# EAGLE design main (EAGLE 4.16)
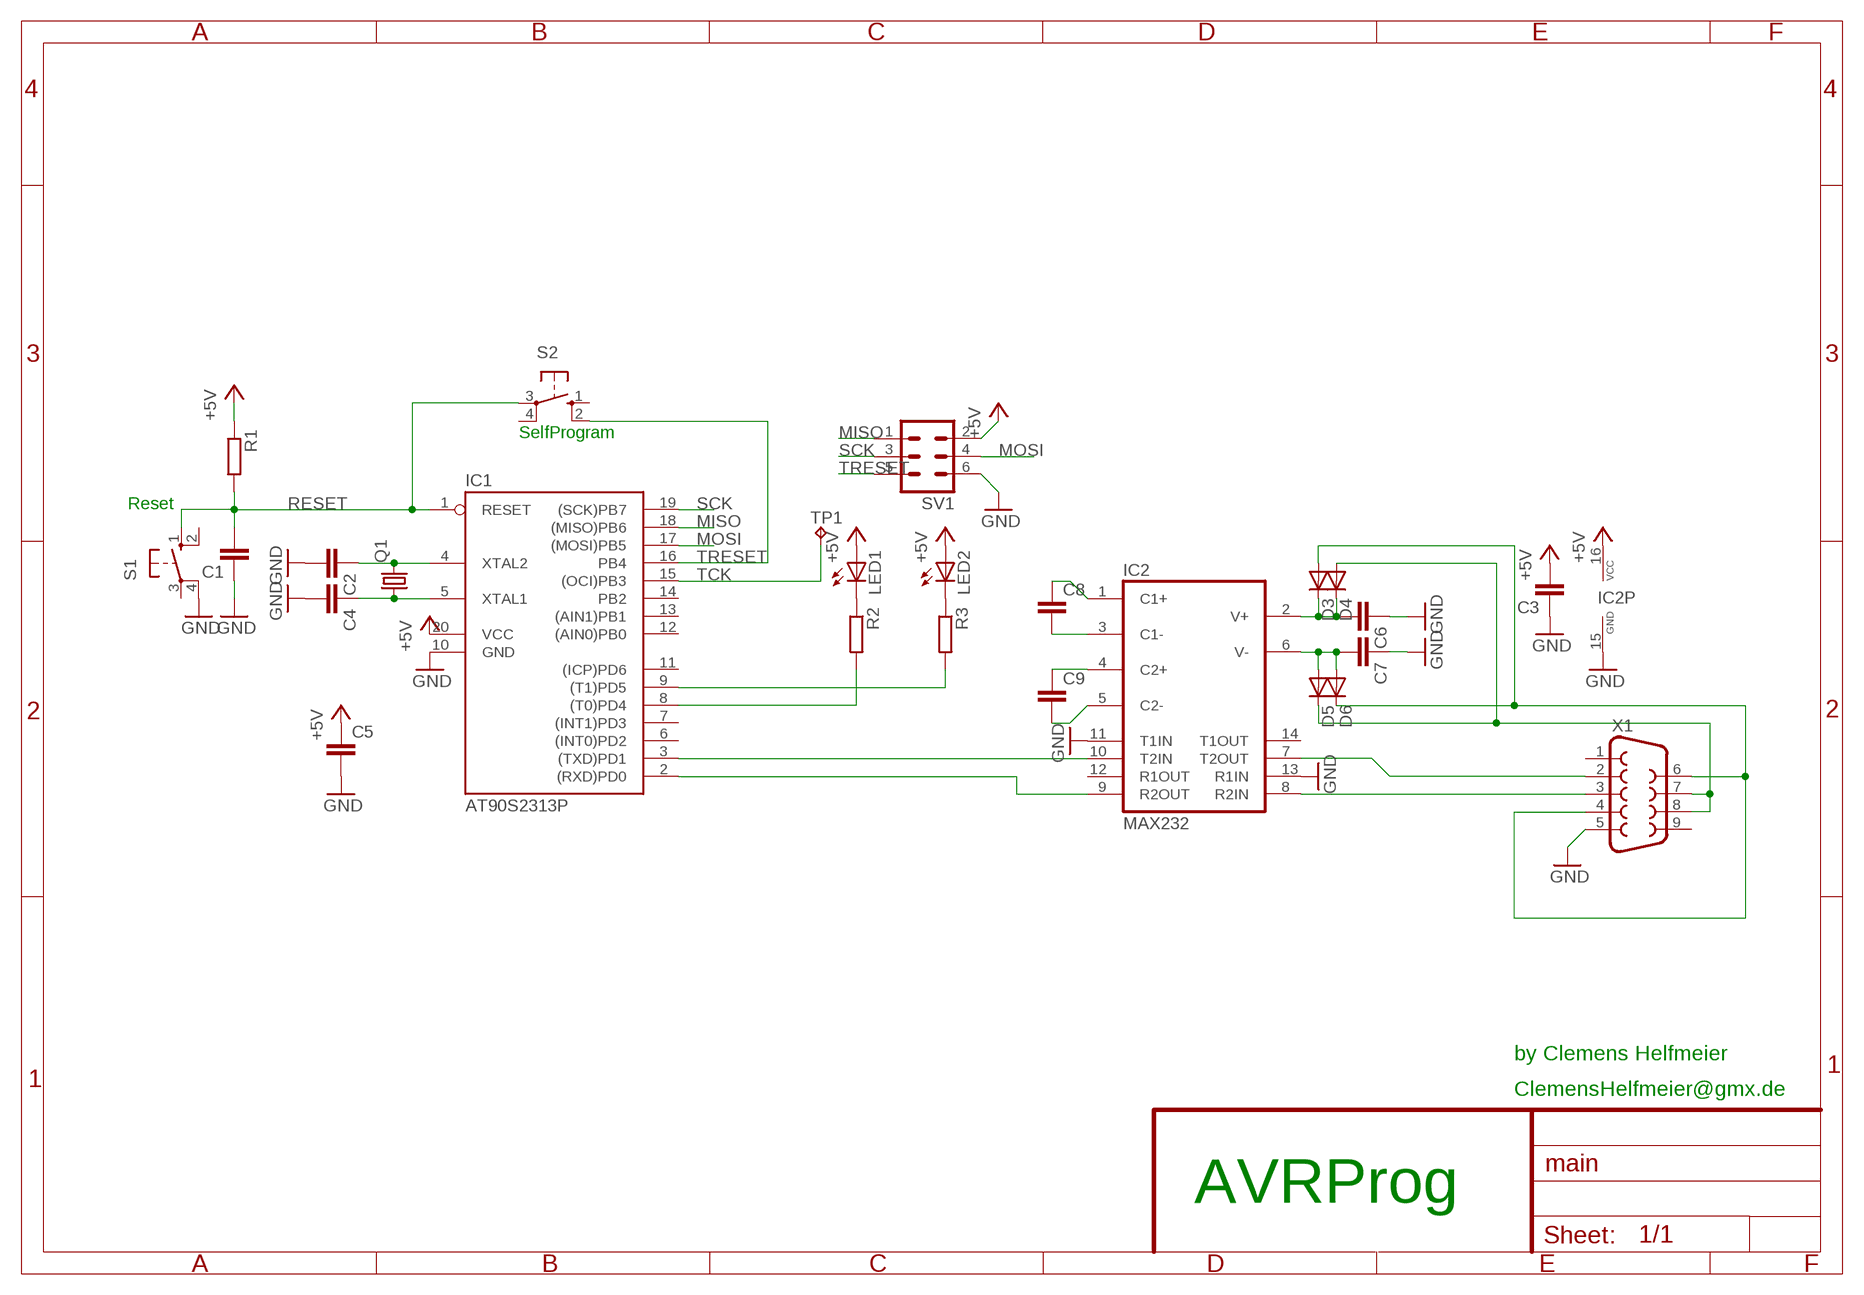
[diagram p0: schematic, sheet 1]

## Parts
C1  C-EU025-024X044  [C025-024X044]
C2  C-EU025-024X044  [C025-024X044]
C3  C-EU025-024X044  [C025-024X044]
C4  C-EU025-024X044  [C025-024X044]
C5  C-EU025-024X044  [C025-024X044]
C6  C-EU025-024X044  [C025-024X044]
C7  C-EU025-024X044  [C025-024X044]
C8  C-EU025-024X044  [C025-024X044]
C9  C-EU025-024X044  [C025-024X044]
D3  DIODE-D-5  [D-5]
D4  DIODE-D-5  [D-5]
D5  DIODE-D-5  [D-5]
D6  DIODE-D-5  [D-5]
IC1  AT90S2313P  [DIL20]
IC2  MAX232  [DIL16]
LED1  LED5MM  [LED5MM]
LED2  LED5MM  [LED5MM]
Q1  CRYTALHC49U-V  [HC49U-V]
R1  R-EU_0204/7  [0204/7]
R2  R-EU_0204/7  [0204/7]
R3  R-EU_0204/7  [0204/7]
S1  10-XX  [B3F-10XX]
S2  10-XX  [B3F-10XX]
SV1  MA03-2W  [MA03-2W]
TP1  TPPAD1-20Y  [P1-20Y]
X1  F09H  [F09H]

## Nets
+5V: C3.2 C5.1 IC1.20(VCC) IC2.16(VCC) LED1.A LED2.A R1.1 SV1.2
GND: C1.1 C2.2 C3.1 C4.2 C5.2 C6.1 C7.1 IC1.10(GND) IC2.11(T1IN) IC2.13(R1IN) IC2.15(GND) S1.4(P1) SV1.6 X1.5
MISO: IC1.18((MISO)PB6) SV1.1
MOSI: IC1.17((MOSI)PB5) SV1.4
N$2: C2.1 IC1.4(XTAL2) Q1.2
N$3: C4.1 IC1.5(XTAL1) Q1.1
N$4: LED1.K(C) R2.1
N$5: LED2.K(C) R3.1
N$6: IC1.8((T0)PD4) R2.2
N$7: IC1.9((T1)PD5) R3.2
N$9: C8.1 IC2.1(C1+)
N$10: C8.2 IC2.3(C1-)
N$11: C9.1 IC2.4(C2+)
N$12: C9.2 IC2.5(C2-)
N$13: C7.2 D5.A D6.A IC2.6(V-)
N$14: C6.2 D3.C D4.C IC2.2(V+)
N$15: IC2.7(T2OUT) X1.2
N$16: IC2.8(R2IN) X1.3
N$17: D3.A D6.C X1.4 X1.6
N$18: D4.A D5.C X1.7 X1.8
N$20: IC1.3((TXD)PD1) IC2.10(T2IN)
N$21: IC1.2((RXD)PD0) IC2.9(R2OUT)
RESET: C1.2 IC1.1(RESET) R1.2 S1.1(S) S2.3(P)
SCK: IC1.19((SCK)PB7) SV1.3
TCK: IC1.15((OCI)PB3) TP1.1(TP)
TRESET: IC1.16(PB4) S2.2(S1) SV1.5
Unconnected: IC1.6((INT0)PD2) IC1.7((INT1)PD3) IC1.11((ICP)PD6) IC1.12((AIN0)PB0) IC1.13((AIN1)PB1) IC1.14(PB2) IC2.12(R1OUT) IC2.14(T1OUT) S1.2(S1) S1.3(P) S2.1(S) S2.4(P1) X1.1 X1.9

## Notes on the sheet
- SelfProgram
- Reset
- by Clemens Helfmeier
- ClemensHelfmeier@gmx.de
- AVRProg

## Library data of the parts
C1-C9 = rcl:C-EU: CAPACITOR, European symbol
D3-D6 = diode:DIODE-: DIODE
IC1 = atmel:AT90S2313: MICROCONTROLLER 2 Kbytes FLASH 128 bytes SRAM 128 bytes EEPROM UART
IC2 = maxim:MAX232: RS232 TRANSEIVER
LED1 LED2 = led:LED: LED
Q1 = crystal:CRYTAL: CRYSTAL
R1-R3 = rcl:R-EU_: RESISTOR, European symbol
S1 S2 = switch-omron:10-XX: OMRON SWITCH
SV1 = atmega162:MA03-2: PIN HEADER
TP1 = testpad:TP
X1 = con-subd:F09: SUB-D

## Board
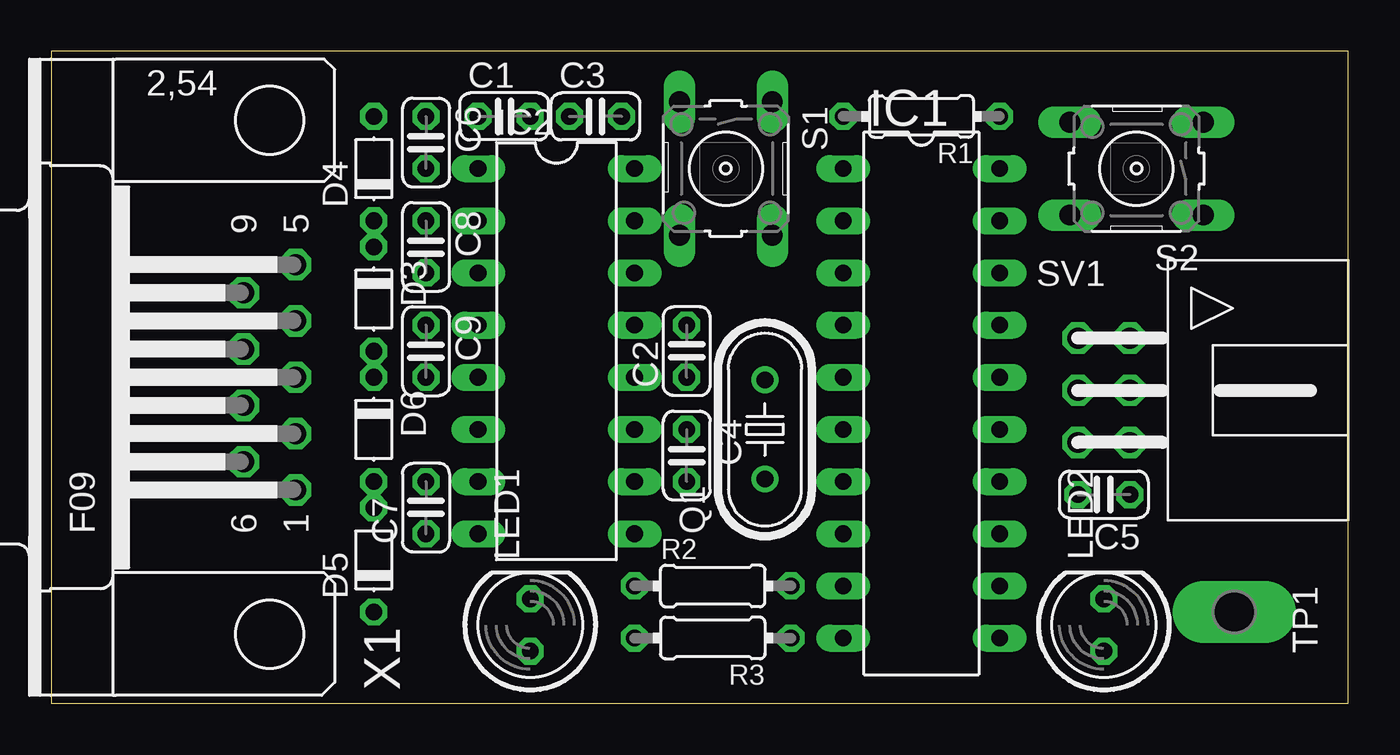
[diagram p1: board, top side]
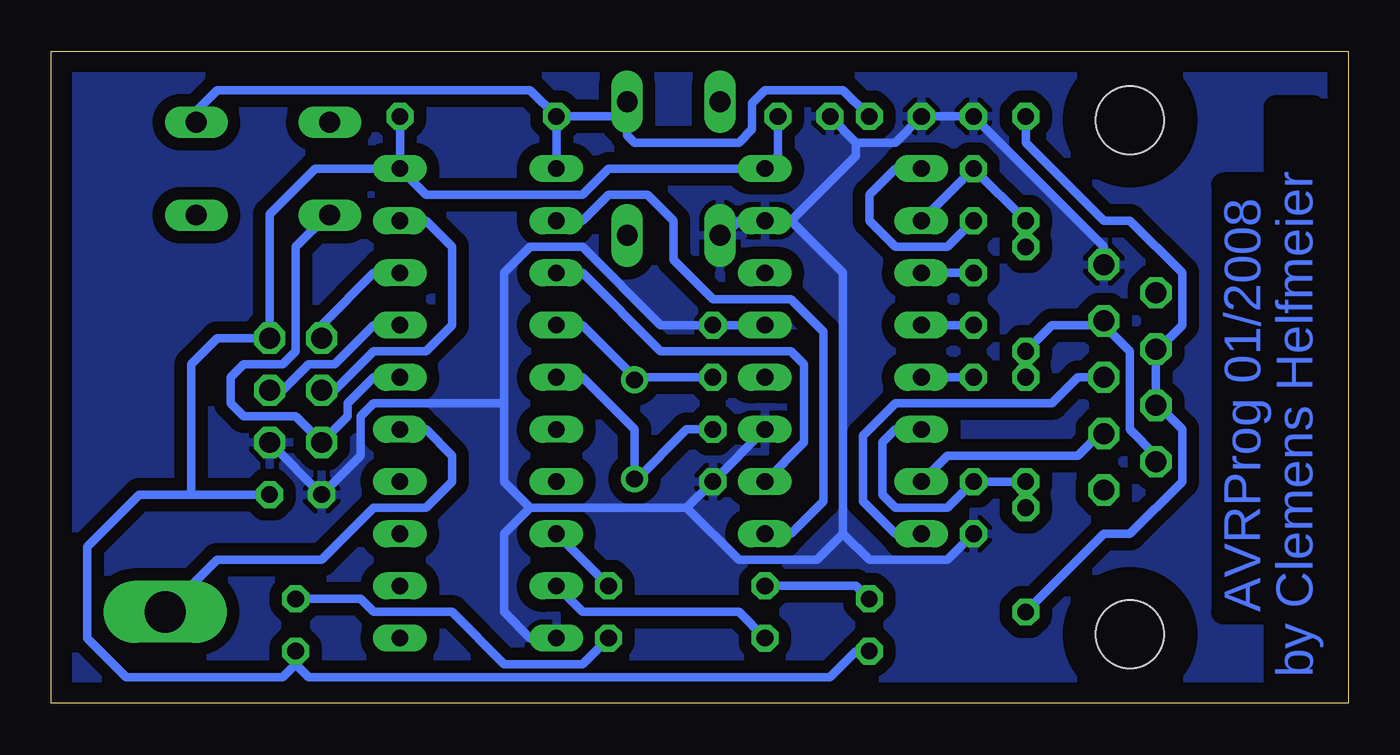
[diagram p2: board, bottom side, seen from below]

Size 63.17 x 31.74 mm. Coordinates in mm from the lower left corner, seen from the top.
Outline: 0,0 63.17,0 63.17,31.74 0,31.74 0,0
Copper layers (1*16): Top 0.035mm / dielectric 1.5mm / Bottom 0.035mm
Design rules "homebrew": minimum track width 16mil, minimum drill 0.8mm, track to track 0.25mm, track to pad 0.25mm, pad to pad 0.25mm, via to via 0.25mm, smd to smd 8mil, copper to edge 40mil, drill to drill 0.5mm, minimum pad ring 0.25mm, minimum via ring 0.25mm, stop-mask expansion 0.15mm, vias tented up to drill 0mil, thermal gap 10mil

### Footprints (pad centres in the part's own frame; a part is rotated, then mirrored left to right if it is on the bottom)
C025-024X044 = drill 0.813 octagon: 1 -1.27,0; 2 1.27,0
D-5 = drill 0.813 octagon: A 2.54,0; C -2.54,0
DIL20 = drill 0.813 long: 1 -11.43,-3.81; 2 -8.89,-3.81; 3 -6.35,-3.81; 4 -3.81,-3.81; 5 -1.27,-3.81; 6 1.27,-3.81; 7 3.81,-3.81; 8 6.35,-3.81; 9 8.89,-3.81; 10 11.43,-3.81; 11 11.43,3.81; 12 8.89,3.81; 13 6.35,3.81; 14 3.81,3.81; 15 1.27,3.81; 16 -1.27,3.81; 17 -3.81,3.81; 18 -6.35,3.81; 19 -8.89,3.81; 20 -11.43,3.81
DIL16 = drill 0.813 long: 1 -8.89,-3.81; 2 -6.35,-3.81; 3 -3.81,-3.81; 4 -1.27,-3.81; 5 1.27,-3.81; 6 3.81,-3.81; 7 6.35,-3.81; 8 8.89,-3.81; 9 8.89,3.81; 10 6.35,3.81; 11 3.81,3.81; 12 1.27,3.81; 13 -1.27,3.81; 14 -3.81,3.81; 15 -6.35,3.81; 16 -8.89,3.81
LED5MM = drill 0.813 octagon: A -1.27,0; K 1.27,0
HC49U-V = drill 0.813 round: 1 -2.413,0; 2 2.413,0
0204/7 = drill 0.813 octagon: 1 -3.81,0; 2 3.81,0
B3F-10XX = drill 1.016 long: 1 -3.251,2.261; 2 3.251,2.261; 3 -3.251,-2.261; 4 3.251,-2.261
MA03-2W = drill 1.016 octagon: 1 -2.54,-2.54; 2 -2.54,0; 3 0,-2.54; 4 0,0; 5 2.54,-2.54; 6 2.54,0
P1-20Y = drill 2.007 pad 2.54 long: 1 0,0
F09H = drill 1.016 octagon: 1 -5.486,-1.27; 2 -2.743,-1.27; 3 0,-1.27; 4 2.743,-1.27; 5 5.486,-1.27; 6 -4.115,1.27; 7 -1.372,1.27; 8 1.372,1.27; 9 4.115,1.27 | hole 3.302: -12.522,0; 12.522,0

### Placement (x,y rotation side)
C1  22.06,28.57 0 top
C2  30.95,17.14 90 top
C3  26.5,28.57 0 top
C4  30.95,12.06 270 top
C5  51.27,10.16 180 top
C6  18.25,27.3 270 top
C7  18.25,9.52 90 top
C8  18.25,22.22 270 top
C9  18.25,17.14 270 top
D3  15.71,19.68 270 top
D4  15.71,26.03 90 top
D5  15.71,6.98 90 top
D6  15.71,13.33 270 top
IC1  42.38,14.6 270 top
IC2  24.6,17.14 270 top
LED1  23.33,3.8 90 top
LED2  51.27,3.8 90 top
Q1  34.76,13.33 90 top
R1  42.38,28.57 180 top
R2  32.22,5.71 0 top
R3  32.22,3.17 180 top
S1  32.85,26.03 270 top
S2  52.86,26.03 180 top
SV1  52.54,15.24 270 top
TP1  57.62,4.44 270 top
X1  10.63,15.87 90 top

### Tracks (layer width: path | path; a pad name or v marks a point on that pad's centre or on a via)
+5V
  Bottom 0.406: IC1.20 R1.1 | LED1.A 23.96,2.54 25.23,1.27 50.63,1.27 51.27,1.9 | 51.27,1.9 LED2.A | 51.27,1.9 51.91,1.27 59.52,1.27 61.43,3.17 61.43,7.62 58.89,10.16 56.35,10.16 | 56.35,10.16 C5.1 | 56.35,10.16 56.35,16.5 55.08,17.77 SV1.2 52.54,23.81 50.32,26.03 IC1.20 | IC1.20 44.92,24.76 37.3,24.76 36.03,26.03 IC2.16 27.77,26.66 C3.2
GND
  Bottom 0.406: 11.9,20.95 X1.5 11.9,22.22 C6.1 C1.1 22.06,27.3 23.96,27.3 | IC2.13 C2.2 33.49,18.41 37.3,22.22 39.84,22.22 41.11,20.95 41.11,14.6 | IC2.11 C4.2 32.22,9.52 | 32.22,9.52 39.84,9.52 | IC1.10 39.84,3.17 41.11,4.44 41.11,8.25 39.84,9.52 | 41.11,14.6 41.11,10.79 39.84,9.52 | 24.6,8.25 24.6,20.95 27.14,23.49 | 24.6,8.25 25.87,6.98 29.68,6.98 32.22,9.52 | 41.11,14.6 47.46,14.6 48.09,13.97 48.09,12.06 C5.2 SV1.6 | 23.96,27.3 C3.1 | S1.4 30.39,22.78 29.68,23.49 IC2.15 27.14,23.49 | 23.96,27.3 23.96,26.66 27.14,23.49 | C7.1 19.52,6.98 23.33,6.98 24.6,8.25
  pour Bottom (isolate 0.61): 0.47,31.11 0.47,0.63 62.7,0.63 62.7,31.11
MISO
  Bottom 0.406: SV1.1 50,18.41 47.46,20.95 IC1.18
MOSI
  Bottom 0.406: IC1.17 47.46,18.41 49.37,16.5 50.63,16.5 51.91,15.24 SV1.4
N$2
  Bottom 0.406: IC1.4 37.3,18.41 34.76,15.87 | 34.76,15.87 Q1.2 | C2.1 34.76,15.87
N$3
  Bottom 0.406: C4.1 32.22,13.33 34.76,10.79 | IC1.5 37.3,15.87 34.76,13.33 34.76,10.79 | 34.76,10.79 Q1.1
N$4
  Bottom 0.406: R2.1 23.96,5.71 LED1.K
N$5
  Bottom 0.406: LED2.K 48.09,5.08 47.46,4.44 43.65,4.44 41.11,1.9 37.3,1.9 R3.1
N$6
  Bottom 0.406: R2.2 IC1.8
N$7
  Bottom 0.406: IC1.9 37.3,4.44 29.68,4.44 R3.2
N$9
  Bottom 0.406: C8.1 19.52,22.22 22.06,22.22 23.33,23.49 23.33,24.76 22.06,26.03 IC2.1
N$10
  Bottom 0.406: C8.2 IC2.3
N$11
  Bottom 0.406: C9.1 IC2.4
N$12
  Bottom 0.406: C9.2 IC2.5
N$13
  Bottom 0.406: D5.A D6.A C7.2 19.52,9.52 22.06,9.52 22.7,10.16 22.7,12.7 22.06,13.33 IC2.6
N$14
  Bottom 0.406: IC2.2 C6.2 D4.C D3.C
N$15
  Bottom 0.406: IC2.7 19.52,12.06 13.17,12.06 11.9,13.33 X1.2
N$16
  Bottom 0.406: X1.3 13.17,15.87 14.44,14.6 22.06,14.6 23.65,13.01 23.65,9.84 22.06,8.25 IC2.8
N$17
  Bottom 0.406: D6.C D3.A 14.44,18.41 11.9,18.41 | X1.6 9.36,12.06 10.63,13.33 10.63,17.14 11.9,18.41 | 11.9,18.41 X1.4
N$18
  Bottom 0.406: 9.36,17.14 X1.7 9.26,14.5 8.09,13.33 8.09,10.79 10.63,8.25 11.9,8.25 D5.C | D4.A 15.71,27.3 11.9,23.49 10.63,23.49 8.09,20.95 8.09,18.41 9.36,17.14 | 9.36,17.14 X1.8
N$20
  Bottom 0.406: IC2.10 26.5,12.7 26.5,16.5 27.14,17.14 33.49,17.14 37.3,20.95 IC1.3
N$21
  Bottom 0.406: IC2.9 27.14,8.25 25.55,9.84 25.55,18.09 27.14,19.68 30.95,19.68 32.85,21.58 32.85,23.49 34.12,24.76 36.03,24.76 37.3,23.49 IC1.2
RESET
  Bottom 0.406: R1.2 IC1.1 | 35.12,28.57 35.12,27.66 34.76,27.3 29.68,27.3 29.04,27.93 29.04,29.2 28.41,29.84 24.6,29.84 C1.2 | 35.12,28.57 S1.1 | 35.12,28.57 34.76,28.57 | 35.12,28.57 R1.2 | R1.2 39.84,29.84 55.08,29.84 56.35,28.57 56.11,28.33 S2.3
SCK
  Bottom 0.406: IC1.19 44.92,23.49 43.65,22.22 43.65,18.41 44.92,17.14 47.46,17.14 49.37,15.24 SV1.3
TCK
  Bottom 0.406: IC1.15 44.92,13.33 43.65,12.06 43.65,10.79 44.92,9.52 47.46,9.52 50,6.98 55.08,6.98 TP1.1
TRESET
  Bottom 0.406: IC1.16 47.46,15.87 48.73,14.6 48.73,13.97 SV1.5 51.27,13.97 53.81,13.97 54.45,14.6 54.45,15.87 53.81,16.5 51.91,16.5 51.27,17.14 51.27,22.22 49.72,23.77 S2.2

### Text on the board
Bottom: AVRProg 01/2008 | by Clemens Helfmeier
